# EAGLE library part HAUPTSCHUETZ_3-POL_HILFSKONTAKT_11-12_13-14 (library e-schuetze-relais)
Hauptschütz mit Öffner und Schließer
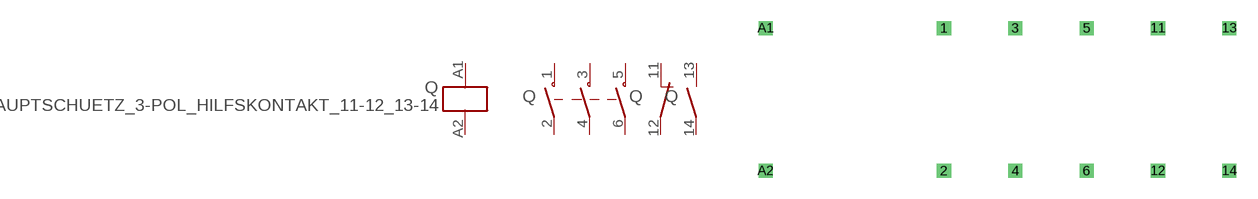
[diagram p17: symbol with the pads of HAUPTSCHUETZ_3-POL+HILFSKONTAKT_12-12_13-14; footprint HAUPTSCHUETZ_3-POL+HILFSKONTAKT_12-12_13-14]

Designator prefix Q; gates G$1=SPULE G$2=SCHLIESSER_HAUPTSCHUETZ_3-POL G$3=OEFFNER G$4=SCHLIESSER

## HAUPTSCHUETZ_3-POL_HILFSKONTAKT_11-12_13-14  [HAUPTSCHUETZ_3-POL+HILFSKONTAKT_12-12_13-14]
1  G$2:1  pas
2  G$2:2  pas
3  G$2:3  pas
4  G$2:4  pas
5  G$2:5  pas
6  G$2:6  pas
11  G$3:1  pas
12  G$3:2  pas
13  G$4:3  pas
14  G$4:4  pas
A1  G$1:A1  in
A2  G$1:A2  in

## Footprint HAUPTSCHUETZ_3-POL+HILFSKONTAKT_12-12_13-14 (pad centres in mm)
Dummy
drill 0.5 pad 1 square: 1 2.54,2.54; 2 2.54,-7.62; 3 7.62,2.54; 4 7.62,-7.62; 5 12.7,2.54; 6 12.7,-7.62; 11 17.78,2.54; 12 17.78,-7.62; 13 22.86,2.54; 14 22.86,-7.62; A1 -10.16,2.54; A2 -10.16,-7.62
